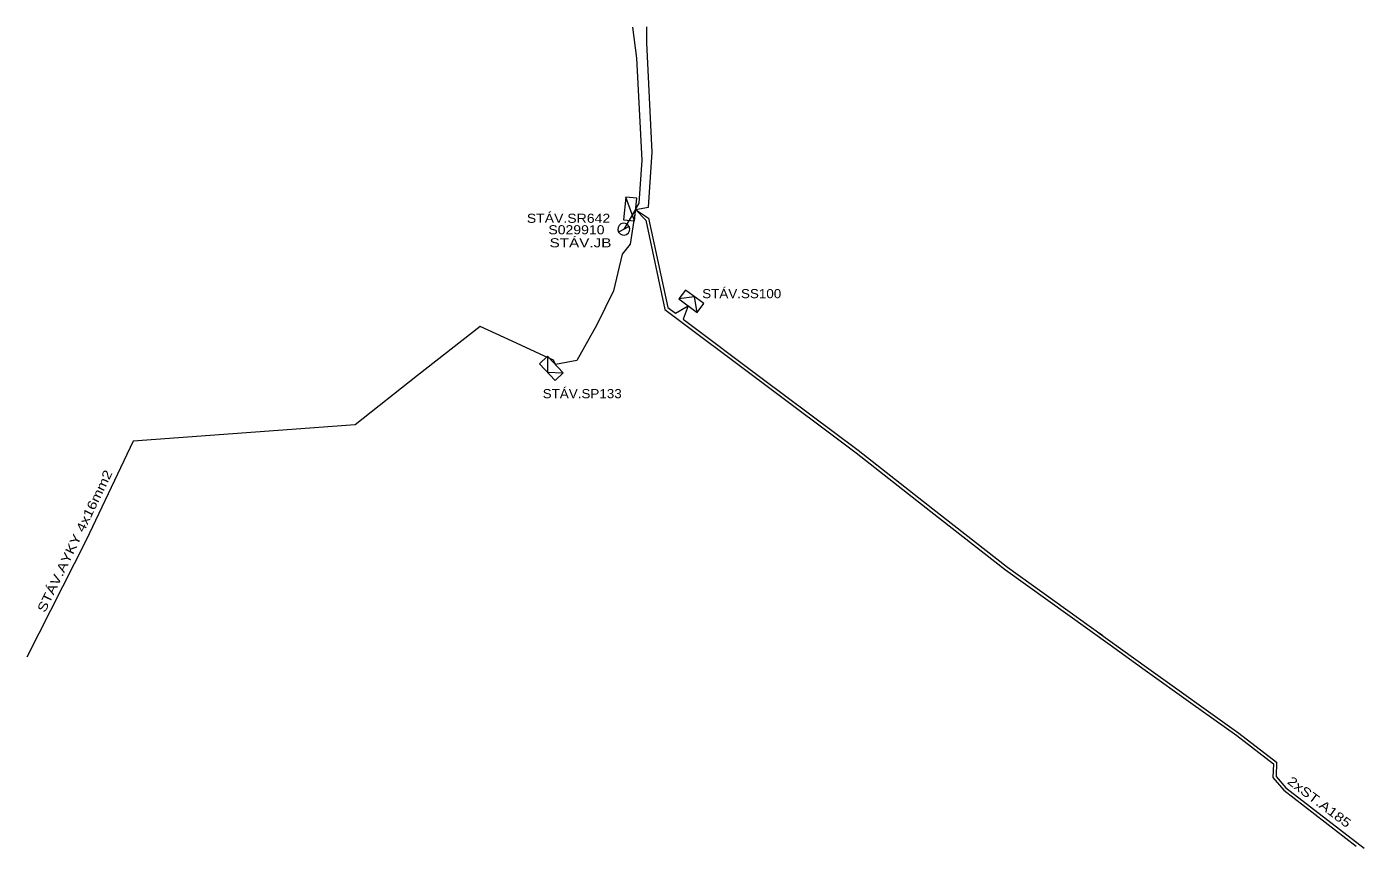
# Model space of a CAD drawing. Extents: x -787638 to -786771, y -1153867 to -1153098.
# Drawn here: x -787332.4 to -787185.7, y -1153279.5 to -1153189.4 of the extents above; entities that cross this region are included whole.
import ezdxf

# ---------------------------------------------------------------- set-up
doc = ezdxf.new("R2010")
doc.units = 0
doc.header["$LTSCALE"] = 0.8
for name, color, linetype in [('10', 7, 'Continuous'), ('20', 7, 'Continuous'), ('42', 7, 'Continuous')]:
    doc.layers.add(name, color=color, linetype=linetype)
for name, color, linetype, lineweight in [('19', 7, 'Continuous', 13), ('41', 7, 'Continuous', 13), ('9', 7, 'Continuous', 13)]:
    doc.layers.add(name, color=color, linetype=linetype, lineweight=lineweight)

msp = doc.modelspace()

# ---------------------------------------------------------------- linework, layer by layer
at = {"layer": '19'}
msp.add_line((-787265.754, -1153210.686), (-787266.693, -1153208.076), dxfattribs=at)
for points in [[(-787265.754, -1153210.686), (-787265.5, -1153208.198), (-787266.693, -1153208.076), (-787266.948, -1153210.563)], [(-787258.16, -1153219.751), (-787260.176, -1153218.274), (-787260.886, -1153219.242), (-787258.868, -1153220.72)], [(-787276.162, -1153226.346), (-787274.454, -1153228.17), (-787273.578, -1153227.35), (-787275.286, -1153225.526)]]:
    msp.add_lwpolyline(points, close=True, dxfattribs=at)
for points in [[(-787258.868, -1153220.72), (-787259.168, -1153219.013), (-787260.886, -1153219.242)], [(-787275.286, -1153225.526), (-787275.308, -1153227.258), (-787273.578, -1153227.35)]]:
    msp.add_lwpolyline(points, dxfattribs=at)
at = {"layer": '41'}
msp.add_line((-787265.627, -1153209.442), (-787266.93, -1153211.59), dxfattribs=at)
for points in [[(-787265.627, -1153209.442), (-787265.26, -1153208.73), (-787264.92, -1153204), (-787265.51, -1153192.83), (-787265.943, -1153189.423)], [(-787265.627, -1153209.442), (-787264.21, -1153209.16), (-787263.83, -1153203.14), (-787264.39, -1153191.15), (-787264.398, -1153189.377)], [(-787265.627, -1153209.442), (-787266.224, -1153213.213), (-787267.11, -1153214.34), (-787268.07, -1153218.33), (-787269.88, -1153222.08), (-787272.07, -1153225.98), (-787274.432, -1153226.438)], [(-787265.627, -1153209.442), (-787264.524, -1153210.601), (-787262.424, -1153220.379), (-787251.946, -1153228.24), (-787241.445, -1153236.12), (-787233.247, -1153242.539), (-787225.052, -1153248.956), (-787213.604, -1153257.168), (-787209.741, -1153259.95), (-787204.748, -1153263.526), (-787199.694, -1153267.141), (-787195.689, -1153270.228), (-787195.732, -1153271.738), (-787194.554, -1153273.131), (-787190.014, -1153276.631), (-787186.602, -1153279.261)], [(-787265.627, -1153209.442), (-787264.212, -1153210.389), (-787262.109, -1153220.177), (-787261.268, -1153220.803), (-787259.877, -1153219.981), (-787260.415, -1153221.443), (-787251.736, -1153227.96), (-787241.232, -1153235.842), (-787233.031, -1153242.263), (-787224.842, -1153248.676), (-787214.48, -1153256.114), (-787214.779, -1153255.899), (-787209.598, -1153259.626), (-787199.485, -1153266.86), (-787195.334, -1153270.06), (-787195.378, -1153271.614), (-787194.311, -1153272.877), (-787185.723, -1153279.497)], [(-787274.432, -1153226.438), (-787274.63, -1153225.96), (-787275.636, -1153225.497), (-787279.163, -1153223.873), (-787282.69, -1153222.25), (-787289.535, -1153227.64), (-787296.38, -1153233.03), (-787320.74, -1153234.85), (-787325.89, -1153245.71), (-787332.405, -1153258.547)]]:
    msp.add_lwpolyline(points, dxfattribs=at)
at = {"layer": '9'}
msp.add_line((-787266.356, -1153211.286), (-787267.504, -1153211.894), dxfattribs=at)
for start, end in [(27.91959, 207.91959), (207.91959, 27.91959)]:
    msp.add_arc((-787266.93, -1153211.59), 0.65, start, end, dxfattribs=at)

# ---------------------------------------------------------------- texts
at = {"layer": '10', "width": 1.25}
msp.add_text('STÁV.JB', height=1, dxfattribs=at).set_placement((-787275.067, -1153213.577))
at = {"layer": '20'}
for s, width, p in [('STÁV.SR642', 1.15, (-787277.566, -1153210.887)), ('S029910', 1.15, (-787275.2, -1153212.148)), ('STÁV.SS100', 1.1, (-787258.328, -1153219.154)), ('STÁV.SP133', 1.1, (-787275.822, -1153230.126))]:
    msp.add_text(s, height=1, dxfattribs=dict(at, width=width)).set_placement(p)
at = {"layer": '42', "width": 1.25}
for s, rotation, p in [('STÁV.AYKY 4x16mm2', 64.228, (-787330.401, -1153253.705)), ('2xST.A185', 322.987, (-787194.248, -1153272.329))]:
    msp.add_text(s, height=1, rotation=rotation, dxfattribs=at).set_placement(p)

doc.saveas('drawing.dxf')
